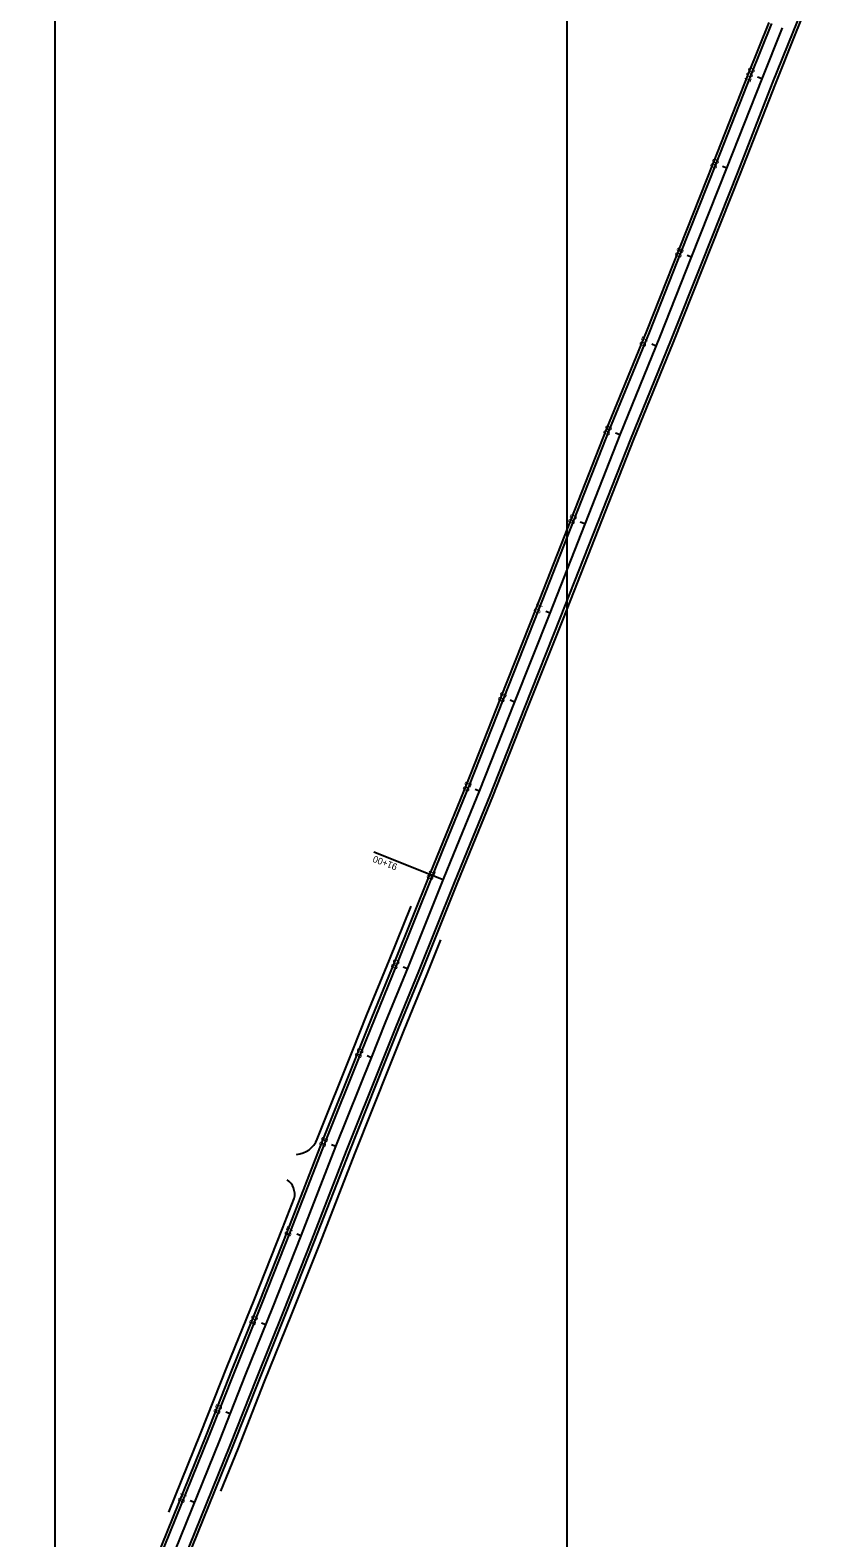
# Model space of a CAD drawing. Extents: x 2318076 to 2324211, y 613525 to 630327.
# Drawn here: x 2319258 to 2320075, y 623105 to 624679 of the extents above; entities that cross this region are included whole.
import ezdxf

# ---------------------------------------------------------------- set-up
doc = ezdxf.new("R2010")
doc.units = 0
for name, color, linetype in [('GE_P_CL_50', 7, 'Continuous'), ('PV_P_EOP', 7, 'Continuous'), ('PV_P_Shoulder', 7, 'Continuous'), ('RD_X_GR_Lt', 7, 'Continuous'), ('RD_X_GR_Rt', 7, 'Continuous'), ('SC_Scratch3', 7, 'Continuous')]:
    doc.layers.add(name, color=color, linetype=linetype)

msp = doc.modelspace()

# ---------------------------------------------------------------- linework, layer by layer
at = {"layer": 'GE_P_CL_50'}
for p, q in [((2320022, 624628), (2320017.3, 624629.8)), ((2319985.3, 624534.9), (2319980.7, 624536.8)), ((2319948.4, 624442), (2319943.8, 624443.8)), ((2319911.4, 624349.1), (2319906.8, 624351)), ((2319873.7, 624256.5), (2319869, 624258.3)), ((2319836.8, 624163.5), (2319832.2, 624165.4)), ((2319800.9, 624070.2), (2319796.3, 624072.1)), ((2319763.5, 623977.5), (2319758.9, 623979.4)), ((2319726.9, 623884.4), (2319722.3, 623886.2)), ((2319689.1, 623791.8), (2319616.7, 623820.8)), ((2319689.1, 623791.8), (2319684.4, 623793.7)), ((2319651.9, 623699), (2319647.3, 623700.9)), ((2319614.3, 623606.3), (2319609.7, 623608.2)), ((2319577.1, 623513.5), (2319572.5, 623515.4)), ((2319540.9, 623420.3), (2319536.3, 623422.1)), ((2319504, 623327.4), (2319499.3, 623329.2)), ((2319466.8, 623234.5), (2319462.1, 623236.4)), ((2319429.5, 623141.8), (2319424.8, 623143.6))]:
    msp.add_line(p, q, dxfattribs=at)
msp.add_lwpolyline([(2319271.8, 622752.1), (2319455.4, 623205.9), (2319483.2, 623276), (2319511.3, 623345.5), (2319540.9, 623420.3), (2319577.1, 623513.5), (2319614.3, 623606.3), (2319629, 623643.1), (2319652.5, 623700.6), (2319689.4, 623792.6), (2319700.1, 623819.1), (2319726.9, 623884.4), (2319763, 623976.2), (2319763, 623976.2), (2319800.6, 624070.3), (2319873.7, 624256.5), (2319915.5, 624359), (2319948.4, 624442), (2319985.3, 624534.9), (2320021.9, 624628), (2320043.3, 624681.5)], dxfattribs=at)
at = {"layer": 'PV_P_EOP'}
for points in [[(2319282.9, 622747.5), (2319466.6, 623201.5), (2319494.4, 623271.6), (2319522.4, 623341), (2319552.1, 623415.9), (2319588.3, 623509.1), (2319625.5, 623601.9), (2319640.1, 623638.6), (2319663.6, 623696.1), (2319700.5, 623788.1), (2319711.2, 623814.6), (2319738, 623879.9), (2319774.2, 623971.8), (2319811.7, 624065.9), (2319884.8, 624252), (2319926.6, 624354.5), (2319959.6, 624437.5), (2319996.5, 624530.5), (2320033, 624623.6), (2320054.4, 624677), (2320072.2, 624720.6)], [(2319260.7, 622756.6), (2319444.3, 623210.4), (2319472.1, 623280.5), (2319500.1, 623349.9), (2319529.8, 623424.7), (2319566, 623517.9), (2319603.2, 623610.8), (2319617.9, 623647.6), (2319641.4, 623705.1), (2319678.2, 623797), (2319689, 623823.7), (2319715.8, 623888.9), (2319751.9, 623980.7), (2319789.4, 624074.7), (2319862.5, 624260.9), (2319904.3, 624363.5), (2319937.3, 624446.4), (2319974.2, 624539.3), (2320010.7, 624632.4), (2320032.2, 624686)]]:
    msp.add_lwpolyline(points, dxfattribs=at)
at = {"layer": 'PV_P_Shoulder'}
for points in [[(2319285.7, 622746.4), (2319469.4, 623200.3), (2319497.2, 623270.4), (2319525.2, 623339.9), (2319554.9, 623414.8), (2319591.1, 623508), (2319628.3, 623600.8), (2319642.9, 623637.4), (2319666.4, 623694.9), (2319703.3, 623787), (2319714, 623813.5), (2319740.8, 623878.8), (2319777, 623970.7), (2319814.5, 624064.8), (2319887.6, 624250.9), (2319929.4, 624353.4), (2319999.3, 624529.4), (2320035.8, 624622.5), (2320057.2, 624675.9), (2320074.9, 624719.5)], [(2319257.9, 622757.8), (2319441.5, 623211.5), (2319469.3, 623281.6), (2319497.3, 623351.1), (2319527, 623425.8), (2319563.2, 623519), (2319600.4, 623611.9), (2319615.1, 623648.7), (2319638.6, 623706.2), (2319675.5, 623798.2), (2319686.2, 623824.8), (2319713, 623890), (2319749.1, 623981.8), (2319786.6, 624075.9), (2319859.7, 624262.1), (2319901.6, 624364.6), (2319971.4, 624540.4), (2320007.9, 624633.5), (2320029.4, 624687.1)]]:
    msp.add_lwpolyline(points, dxfattribs=at)
at = {"layer": 'RD_X_GR_Lt'}
for points in [[(2319557.5, 623521), (2319557.6, 623521.2), (2319594.8, 623614.1), (2319609.5, 623650.9), (2319633.1, 623708.4), (2319655.5, 623764.5)], [(2319402.7, 623131.7), (2319435.9, 623213.7), (2319463.7, 623283.8), (2319491.8, 623353.3), (2319521.4, 623428), (2319533.6, 623459.4)]]:
    msp.add_lwpolyline(points, dxfattribs=at)
for centre, radius, start, end in [((2319534.4, 623530.1), 24.8, 273.5693, 339.0635), ((2319515.2, 623463.6), 18.9, 347.1986, 54.2037)]:
    msp.add_arc(centre, radius, start, end, dxfattribs=at)
at = {"layer": 'RD_X_GR_Rt'}
msp.add_lwpolyline([(2319457, 623153.7), (2319474.9, 623198.1), (2319502.7, 623268.2), (2319530.8, 623337.7), (2319560.5, 623412.6), (2319596.7, 623505.8), (2319633.8, 623598.5), (2319648.5, 623635.2), (2319672, 623692.7), (2319686.7, 623729.4)], dxfattribs=at)
at = {"layer": 'SC_Scratch3'}
for p, q in [((2319283.9, 614778.4), (2319283.9, 630327.2)), ((2319818.5, 614778.4), (2319818.5, 630327.2))]:
    msp.add_line(p, q, dxfattribs=at)

# ---------------------------------------------------------------- texts
at = {"layer": 'GE_P_CL_50'}
for s, rotation, p in [('100', 68.9386, (2320009.4, 624623.8)), ('99', 68.0441, (2319973.8, 624533.6)), ('98', 68.3817, (2319936.8, 624440.6)), ('97', 67.9306, (2319899.8, 624347.6)), ('96', 68.5456, (2319862.1, 624255)), ('95', 67.9965, (2319825.3, 624162.3)), ('94', 67.9955, (2319789.4, 624069)), ('93', 67.3411, (2319752, 623976.4)), ('92', 68.3373, (2319715.4, 623883.2)), ('91+00', 159.2418, (2319641.9, 623808.2)), ('91', 68.0408, (2319677.7, 623791)), ('90', 67.7618, (2319640.3, 623697.7)), ('89', 68.2266, (2319602.8, 623605)), ('88', 68.1454, (2319565.6, 623512.2)), ('87', 68.3591, (2319529.3, 623418.7)), ('86', 68.0338, (2319492.4, 623326)), ('85', 68.358, (2319455.2, 623233.2)), ('84', 68.5128, (2319418, 623140.5))]:
    msp.add_text(s, height=7, rotation=rotation, dxfattribs=at).set_placement(p)

doc.saveas('drawing.dxf')
